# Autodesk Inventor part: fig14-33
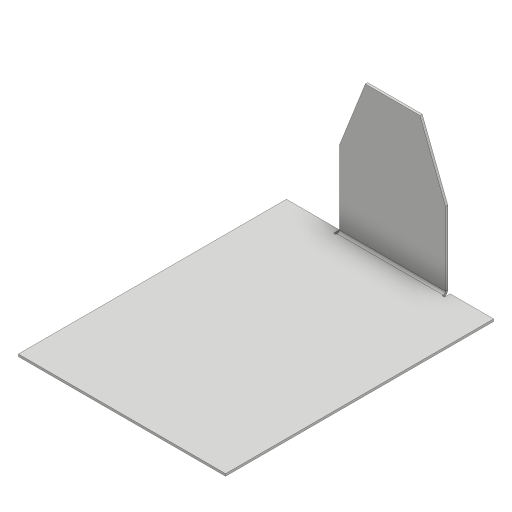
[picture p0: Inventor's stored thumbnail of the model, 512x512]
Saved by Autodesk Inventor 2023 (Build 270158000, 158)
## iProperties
Created: 2017-05
Part Number: fig14-33
Material: Generic
Document SubType Name: Sheet Metal
Designer: CADCIM 00
Density: 1 g/cm^3
Sheet Metal Rule: Default_mm
Appearance: Default
Author: CADCIM 00
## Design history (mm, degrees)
node "Face1"
  sketch "Sketch1"
    geometry: L1 (0, 0)-(45.649, 0); L2 (45.649, 0)-(45.649, 59.054); L3 (45.649, 59.054)-(0, 59.054); L4 (0, 59.054)-(0, 0)
    constraints: 8 end point, 2 parallel, 1 horizontal, 1 perpendicular
node "Face2"
  sketch "Sketch2"
    geometry: L1 (12.162, -17.144)-(17.899, -31.705); L2 (17.899, -31.705)-(29.912, -31.705); L3 (29.912, -31.705)-(35.56, -17.144); L4 (35.56, -17.144)-(12.162, -17.144); 1 further point
    constraints: 8 end point, 1 horizontal, 1 parallel
body "Solid1"
face "Plate1" dims "d0" = 0.5 (= Thickness)
face "Plate2" dims "d0" = 0.5 (= Thickness), "d1" = 0.5 (= BendRadius), "d2" = 0.5 (= BendReliefWidth), "d4" = 1 (= MinimumRemnant)
bend "Bend1" dims "d0" = 0.5 (= Thickness), "d1" = 0.5 (= BendRadius), "d2" = 0.5 (= BendReliefWidth), "d3" = 0.25 (= BendReliefDepth), "d4" = 1 (= MinimumRemnant), "d5" = 0.5 (= TransitionRadius), "SeamGap" = 0.01
other parameters: "Thickness" = 0.5, "BendRadius" = 0.5 (= Thickness), "BendReliefWidth" = 0.5 (= Thickness), "BendReliefDepth" = 0.25 (= 0.5 x Thickness), "CornerReliefSize" = 2 (= 4 x Thickness), "MinimumRemnant" = 1 (= 2 x Thickness), "TransitionRadius" = 0.5 (= BendRadius), "JacobiRadiusSize" = 0.5 (= BendRadius), "GapSize" = 0.5 (= Thickness)
